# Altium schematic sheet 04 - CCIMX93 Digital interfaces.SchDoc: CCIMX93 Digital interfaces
size A3; PageSetup: Record=PageOptions¦CenterHorizontal=True¦CenterVertical=True¦PrintScale=0.70¦XCorrection=1.00¦YCorrection=1.00¦PrintKind=0¦BorderSize=5000000¦LeftOffset=0¦BottomOffset=0¦Orientation=2¦PaperLength=4200¦PaperWidth=2970¦Scale=100¦PaperSource=7¦PrintQuality=600¦MediaType=1¦DitherType=10¦PaperKind=A4¦PrintScaleMode=1; Author: Juan Anzola; SheetNumber: 4; SheetTotal: 20
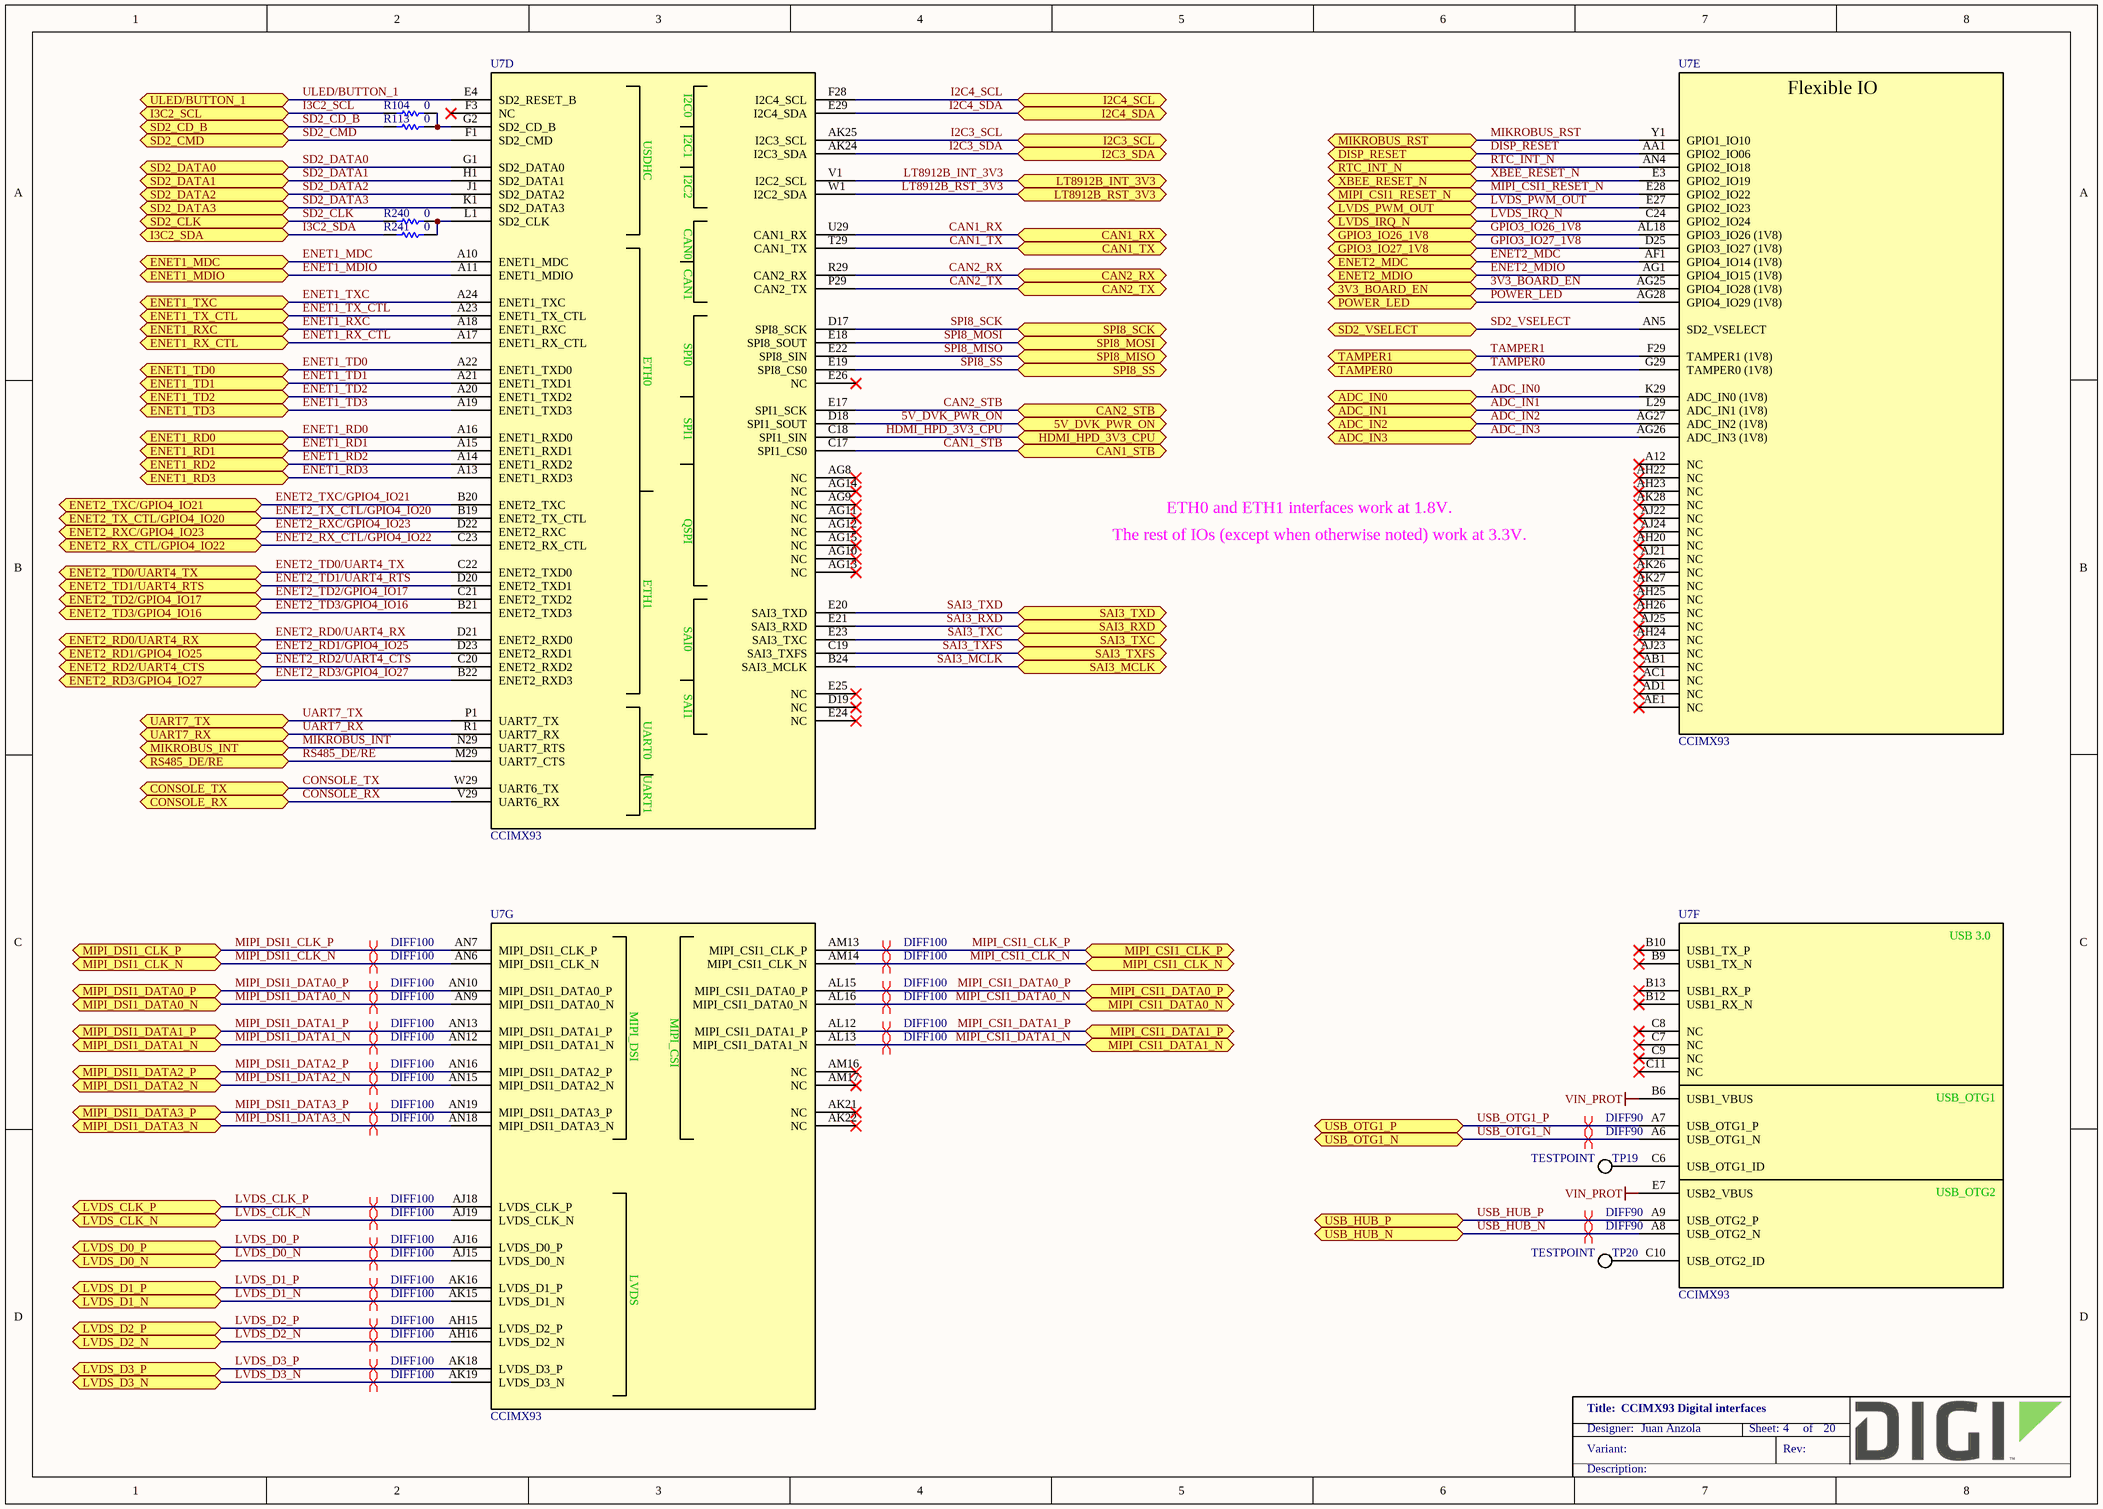
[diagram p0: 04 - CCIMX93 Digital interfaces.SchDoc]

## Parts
R104  0  [RESC1005X40N]
R113  0  [RESC1005X40N]
R240  0  [RESC1005X40N]
R241  0  [RESC1005X40N]
TP19  TESTPOINT  [TP0762]  (no BOM)
TP20  TESTPOINT  [TP0762]  (no BOM)
U7  CCIMX93  [CC93_DVK]  (parts D,E,F,G of 10)

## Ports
3V3_BOARD_EN (bidir), 5V_DVK_PWR_ON (bidir), ADC_IN0 (bidir), ADC_IN1 (bidir), ADC_IN2 (bidir), ADC_IN3 (bidir), CAN1_RX (bidir), CAN1_STB (bidir), CAN1_TX (bidir), CAN2_RX (bidir), CAN2_STB (bidir), CAN2_TX (bidir), CONSOLE_RX (bidir), CONSOLE_TX (bidir), DISP_RESET (bidir), ENET1_MDC (bidir), ENET1_MDIO (bidir), ENET1_RD0 (bidir), ENET1_RD1 (bidir), ENET1_RD2 (bidir), ENET1_RD3 (bidir), ENET1_RX_CTL (bidir), ENET1_RXC (bidir), ENET1_TD0 (bidir), ENET1_TD1 (bidir), ENET1_TD2 (bidir), ENET1_TD3 (bidir), ENET1_TX_CTL (bidir), ENET1_TXC (bidir), ENET2_MDC (bidir), ENET2_MDIO (bidir), ENET2_RD0/UART4_RX (bidir), ENET2_RD1/GPIO4_IO25 (bidir), ENET2_RD2/UART4_CTS (bidir), ENET2_RD3/GPIO4_IO27 (bidir), ENET2_RX_CTL/GPIO4_IO22 (bidir), ENET2_RXC/GPIO4_IO23 (bidir), ENET2_TD0/UART4_TX (bidir), ENET2_TD1/UART4_RTS (bidir), ENET2_TD2/GPIO4_IO17 (bidir), ENET2_TD3/GPIO4_IO16 (bidir), ENET2_TX_CTL/GPIO4_IO20 (bidir), ENET2_TXC/GPIO4_IO21 (bidir), GPIO3_IO26_1V8 (bidir), GPIO3_IO27_1V8 (bidir), HDMI_HPD_3V3_CPU (bidir), I2C3_SCL (bidir), I2C3_SDA (bidir), I2C4_SCL (bidir), I2C4_SDA (bidir), I3C2_SCL (bidir), I3C2_SDA (bidir), LT8912B_INT_3V3 (bidir), LT8912B_RST_3V3 (bidir), LVDS_CLK_N (bidir), LVDS_CLK_P (bidir), LVDS_D0_N (bidir), LVDS_D0_P (bidir), LVDS_D1_N (bidir), LVDS_D1_P (bidir), LVDS_D2_N (bidir), LVDS_D2_P (bidir), LVDS_D3_N (bidir), LVDS_D3_P (bidir), LVDS_IRQ_N (bidir), LVDS_PWM_OUT (bidir), MIKROBUS_INT (bidir), MIKROBUS_RST (bidir), MIPI_CSI1_CLK_N (bidir), MIPI_CSI1_CLK_P (bidir), MIPI_CSI1_DATA0_N (bidir), MIPI_CSI1_DATA0_P (bidir), MIPI_CSI1_DATA1_N (bidir), MIPI_CSI1_DATA1_P (bidir), MIPI_CSI1_RESET_N (bidir), MIPI_DSI1_CLK_N (bidir), MIPI_DSI1_CLK_P (bidir), MIPI_DSI1_DATA0_N (bidir), MIPI_DSI1_DATA0_P (bidir), MIPI_DSI1_DATA1_N (bidir), MIPI_DSI1_DATA1_P (bidir), MIPI_DSI1_DATA2_N (bidir), MIPI_DSI1_DATA2_P (bidir), MIPI_DSI1_DATA3_N (bidir), MIPI_DSI1_DATA3_P (bidir), POWER_LED (bidir), RS485_DE/RE (bidir), RTC_INT_N (bidir), SAI3_MCLK (bidir), SAI3_RXD (bidir), SAI3_TXC (bidir), SAI3_TXD (bidir), SAI3_TXFS (bidir), SD2_CD_B (bidir), SD2_CLK (bidir), SD2_CMD (bidir), SD2_DATA0 (bidir), SD2_DATA1 (bidir), SD2_DATA2 (bidir), SD2_DATA3 (bidir), SD2_VSELECT (bidir), SPI8_MISO (bidir), SPI8_MOSI (bidir), SPI8_SCK (bidir), SPI8_SS (bidir), TAMPER0 (bidir), TAMPER1 (bidir), UART7_RX (bidir), UART7_TX (bidir), ULED/BUTTON_1 (bidir), USB_HUB_N (bidir), USB_HUB_P (bidir), USB_OTG1_N (bidir), USB_OTG1_P (bidir), XBEE_RESET_N (bidir)

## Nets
VIN_PROT: U7.B6(USB1_VBUS) U7.E7(USB2_VBUS)
3V3_BOARD_EN: U7.AG25(GPIO4_IO28_(1V8)) ; port 3V3_BOARD_EN
5V_DVK_PWR_ON: U7.D18(SPI1_SOUT) ; port 5V_DVK_PWR_ON
ADC_IN0: U7.K29(ADC_IN0_(1V8)) ; port ADC_IN0
ADC_IN1: U7.L29(ADC_IN1_(1V8)) ; port ADC_IN1
ADC_IN2: U7.AG27(ADC_IN2_(1V8)) ; port ADC_IN2
ADC_IN3: U7.AG26(ADC_IN3_(1V8)) ; port ADC_IN3
CAN1_RX: U7.U29(CAN1_RX) ; port CAN1_RX
CAN1_STB: U7.C17(SPI1_CS0) ; port CAN1_STB
CAN1_TX: U7.T29(CAN1_TX) ; port CAN1_TX
CAN2_RX: U7.R29(CAN2_RX) ; port CAN2_RX
CAN2_STB: U7.E17(SPI1_SCK) ; port CAN2_STB
CAN2_TX: U7.P29(CAN2_TX) ; port CAN2_TX
CONSOLE_RX: U7.V29(UART6_RX) ; port CONSOLE_RX
CONSOLE_TX: U7.W29(UART6_TX) ; port CONSOLE_TX
DISP_RESET: U7.AA1(GPIO2_IO06) ; port DISP_RESET
ENET1_MDC: U7.A10(ENET1_MDC) ; port ENET1_MDC
ENET1_MDIO: U7.A11(ENET1_MDIO) ; port ENET1_MDIO
ENET1_RD0: U7.A16(ENET1_RXD0) ; port ENET1_RD0
ENET1_RD1: U7.A15(ENET1_RXD1) ; port ENET1_RD1
ENET1_RD2: U7.A14(ENET1_RXD2) ; port ENET1_RD2
ENET1_RD3: U7.A13(ENET1_RXD3) ; port ENET1_RD3
ENET1_RX_CTL: U7.A17(ENET1_RX_CTL) ; port ENET1_RX_CTL
ENET1_RXC: U7.A18(ENET1_RXC) ; port ENET1_RXC
ENET1_TD0: U7.A22(ENET1_TXD0) ; port ENET1_TD0
ENET1_TD1: U7.A21(ENET1_TXD1) ; port ENET1_TD1
ENET1_TD2: U7.A20(ENET1_TXD2) ; port ENET1_TD2
ENET1_TD3: U7.A19(ENET1_TXD3) ; port ENET1_TD3
ENET1_TX_CTL: U7.A23(ENET1_TX_CTL) ; port ENET1_TX_CTL
ENET1_TXC: U7.A24(ENET1_TXC) ; port ENET1_TXC
ENET2_MDC: U7.AF1(GPIO4_IO14_(1V8)) ; port ENET2_MDC
ENET2_MDIO: U7.AG1(GPIO4_IO15_(1V8)) ; port ENET2_MDIO
ENET2_RD0/UART4_RX: U7.D21(ENET2_RXD0) ; port ENET2_RD0/UART4_RX
ENET2_RD1/GPIO4_IO25: U7.D23(ENET2_RXD1) ; port ENET2_RD1/GPIO4_IO25
ENET2_RD2/UART4_CTS: U7.C20(ENET2_RXD2) ; port ENET2_RD2/UART4_CTS
ENET2_RD3/GPIO4_IO27: U7.B22(ENET2_RXD3) ; port ENET2_RD3/GPIO4_IO27
ENET2_RX_CTL/GPIO4_IO22: U7.C23(ENET2_RX_CTL) ; port ENET2_RX_CTL/GPIO4_IO22
ENET2_RXC/GPIO4_IO23: U7.D22(ENET2_RXC) ; port ENET2_RXC/GPIO4_IO23
ENET2_TD0/UART4_TX: U7.C22(ENET2_TXD0) ; port ENET2_TD0/UART4_TX
ENET2_TD1/UART4_RTS: U7.D20(ENET2_TXD1) ; port ENET2_TD1/UART4_RTS
ENET2_TD2/GPIO4_IO17: U7.C21(ENET2_TXD2) ; port ENET2_TD2/GPIO4_IO17
ENET2_TD3/GPIO4_IO16: U7.B21(ENET2_TXD3) ; port ENET2_TD3/GPIO4_IO16
ENET2_TX_CTL/GPIO4_IO20: U7.B19(ENET2_TX_CTL) ; port ENET2_TX_CTL/GPIO4_IO20
ENET2_TXC/GPIO4_IO21: U7.B20(ENET2_TXC) ; port ENET2_TXC/GPIO4_IO21
GPIO3_IO26_1V8: U7.AL18(GPIO3_IO26_(1V8)) ; port GPIO3_IO26_1V8
GPIO3_IO27_1V8: U7.D25(GPIO3_IO27_(1V8)) ; port GPIO3_IO27_1V8
HDMI_HPD_3V3_CPU: U7.C18(SPI1_SIN) ; port HDMI_HPD_3V3_CPU
I2C3_SCL: U7.AK25(I2C3_SCL) ; port I2C3_SCL
I2C3_SDA: U7.AK24(I2C3_SDA) ; port I2C3_SDA
I2C4_SCL: U7.F28(I2C4_SCL) ; port I2C4_SCL
I2C4_SDA: U7.E29(I2C4_SDA) ; port I2C4_SDA
I3C2_SCL: R104.1 ; port I3C2_SCL
I3C2_SDA: R241.1 ; port I3C2_SDA
LT8912B_INT_3V3: U7.V1(I2C2_SCL) ; port LT8912B_INT_3V3
LT8912B_RST_3V3: U7.W1(I2C2_SDA) ; port LT8912B_RST_3V3
LVDS_CLK_N: U7.AJ19(LVDS_CLK_N) ; port LVDS_CLK_N
LVDS_CLK_P: U7.AJ18(LVDS_CLK_P) ; port LVDS_CLK_P
LVDS_D0_N: U7.AJ15(LVDS_D0_N) ; port LVDS_D0_N
LVDS_D0_P: U7.AJ16(LVDS_D0_P) ; port LVDS_D0_P
LVDS_D1_N: U7.AK15(LVDS_D1_N) ; port LVDS_D1_N
LVDS_D1_P: U7.AK16(LVDS_D1_P) ; port LVDS_D1_P
LVDS_D2_N: U7.AH16(LVDS_D2_N) ; port LVDS_D2_N
LVDS_D2_P: U7.AH15(LVDS_D2_P) ; port LVDS_D2_P
LVDS_D3_N: U7.AK19(LVDS_D3_N) ; port LVDS_D3_N
LVDS_D3_P: U7.AK18(LVDS_D3_P) ; port LVDS_D3_P
LVDS_IRQ_N: U7.C24(GPIO2_IO24) ; port LVDS_IRQ_N
LVDS_PWM_OUT: U7.E27(GPIO2_IO23) ; port LVDS_PWM_OUT
MIKROBUS_INT: U7.N29(UART7_RTS) ; port MIKROBUS_INT
MIKROBUS_RST: U7.Y1(GPIO1_IO10) ; port MIKROBUS_RST
MIPI_CSI1_CLK_N: U7.AM14(MIPI_CSI1_CLK_N) ; port MIPI_CSI1_CLK_N
MIPI_CSI1_CLK_P: U7.AM13(MIPI_CSI1_CLK_P) ; port MIPI_CSI1_CLK_P
MIPI_CSI1_DATA0_N: U7.AL16(MIPI_CSI1_DATA0_N) ; port MIPI_CSI1_DATA0_N
MIPI_CSI1_DATA0_P: U7.AL15(MIPI_CSI1_DATA0_P) ; port MIPI_CSI1_DATA0_P
MIPI_CSI1_DATA1_N: U7.AL13(MIPI_CSI1_DATA1_N) ; port MIPI_CSI1_DATA1_N
MIPI_CSI1_DATA1_P: U7.AL12(MIPI_CSI1_DATA1_P) ; port MIPI_CSI1_DATA1_P
MIPI_CSI1_RESET_N: U7.E28(GPIO2_IO22) ; port MIPI_CSI1_RESET_N
MIPI_DSI1_CLK_N: U7.AN6(MIPI_DSI1_CLK_N) ; port MIPI_DSI1_CLK_N
MIPI_DSI1_CLK_P: U7.AN7(MIPI_DSI1_CLK_P) ; port MIPI_DSI1_CLK_P
MIPI_DSI1_DATA0_N: U7.AN9(MIPI_DSI1_DATA0_N) ; port MIPI_DSI1_DATA0_N
MIPI_DSI1_DATA0_P: U7.AN10(MIPI_DSI1_DATA0_P) ; port MIPI_DSI1_DATA0_P
MIPI_DSI1_DATA1_N: U7.AN12(MIPI_DSI1_DATA1_N) ; port MIPI_DSI1_DATA1_N
MIPI_DSI1_DATA1_P: U7.AN13(MIPI_DSI1_DATA1_P) ; port MIPI_DSI1_DATA1_P
MIPI_DSI1_DATA2_N: U7.AN15(MIPI_DSI1_DATA2_N) ; port MIPI_DSI1_DATA2_N
MIPI_DSI1_DATA2_P: U7.AN16(MIPI_DSI1_DATA2_P) ; port MIPI_DSI1_DATA2_P
MIPI_DSI1_DATA3_N: U7.AN18(MIPI_DSI1_DATA3_N) ; port MIPI_DSI1_DATA3_N
MIPI_DSI1_DATA3_P: U7.AN19(MIPI_DSI1_DATA3_P) ; port MIPI_DSI1_DATA3_P
POWER_LED: U7.AG28(GPIO4_IO29_(1V8)) ; port POWER_LED
RS485_DE/RE: U7.M29(UART7_CTS) ; port RS485_DE/RE
RTC_INT_N: U7.AN4(GPIO2_IO18) ; port RTC_INT_N
SAI3_MCLK: U7.B24(SAI3_MCLK) ; port SAI3_MCLK
SAI3_RXD: U7.E21(SAI3_RXD) ; port SAI3_RXD
SAI3_TXC: U7.E23(SAI3_TXC) ; port SAI3_TXC
SAI3_TXD: U7.E20(SAI3_TXD) ; port SAI3_TXD
SAI3_TXFS: U7.C19(SAI3_TXFS) ; port SAI3_TXFS
SD2_CD_B: R113.1 ; port SD2_CD_B
SD2_CLK: R240.1 ; port SD2_CLK
SD2_CMD: U7.F1(SD2_CMD) ; port SD2_CMD
SD2_DATA0: U7.G1(SD2_DATA0) ; port SD2_DATA0
SD2_DATA1: U7.H1(SD2_DATA1) ; port SD2_DATA1
SD2_DATA2: U7.J1(SD2_DATA2) ; port SD2_DATA2
SD2_DATA3: U7.K1(SD2_DATA3) ; port SD2_DATA3
SD2_VSELECT: U7.AN5(SD2_VSELECT) ; port SD2_VSELECT
SPI8_MISO: U7.E22(SPI8_SIN) ; port SPI8_MISO
SPI8_MOSI: U7.E18(SPI8_SOUT) ; port SPI8_MOSI
SPI8_SCK: U7.D17(SPI8_SCK) ; port SPI8_SCK
SPI8_SS: U7.E19(SPI8_CS0) ; port SPI8_SS
TAMPER0: U7.G29(TAMPER0_(1V8)) ; port TAMPER0
TAMPER1: U7.F29(TAMPER1_(1V8)) ; port TAMPER1
UART7_RX: U7.R1(UART7_RX) ; port UART7_RX
UART7_TX: U7.P1(UART7_TX) ; port UART7_TX
ULED/BUTTON_1: U7.E4(SD2_RESET_B) ; port ULED/BUTTON_1
USB_HUB_N: U7.A8(USB_OTG2_N) ; port USB_HUB_N
USB_HUB_P: U7.A9(USB_OTG2_P) ; port USB_HUB_P
USB_OTG1_N: U7.A6(USB_OTG1_N) ; port USB_OTG1_N
USB_OTG1_P: U7.A7(USB_OTG1_P) ; port USB_OTG1_P
XBEE_RESET_N: U7.E3(GPIO2_IO19) ; port XBEE_RESET_N
NetR104_2: R104.2 R113.2 U7.G2(SD2_CD_B)
NetR240_2: R240.2 R241.2 U7.L1(SD2_CLK)
NetTP19_1: TP19.1 U7.C6(USB_OTG1_ID)
NetTP20_1: TP20.1 U7.C10(USB_OTG2_ID)

Not connected (* = marked no-connect by the designer): U7 A12(NC)* AB1(NC)* AC1(NC)* AD1(NC)* AE1(NC)* AG8(NC)* AG9(NC)* AG10(NC)* AG11(NC)* AG12(NC)* AG13(NC)* AG14(NC)* AG15(NC)* AH20(NC)* AH22(NC)* AH23(NC)* AH24(NC)* AH25(NC)* AH26(NC)* AJ21(NC)* AJ22(NC)* AJ23(NC)* AJ24(NC)* AJ25(NC)* AK21(NC)* AK22(NC)* AK26(NC)* AK27(NC)* AK28(NC)* AM16(NC)* AM17(NC)* B9(USB1_TX_N)* B10(USB1_TX_P)* B12(USB1_RX_N)* B13(USB1_RX_P)* C7(NC)* C8(NC)* C9(NC)* C11(NC)* D19(NC)* E24(NC)* E25(NC)* E26(NC)* F3(NC)*

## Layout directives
differential pair; net class DIFF100; differential pair class DIFF100: LVDS_CLK_N, LVDS_CLK_P, LVDS_D0_N, LVDS_D0_P, LVDS_D1_N, LVDS_D1_P, LVDS_D2_N, LVDS_D2_P, LVDS_D3_N, LVDS_D3_P, MIPI_CSI1_CLK_N, MIPI_CSI1_CLK_P, MIPI_CSI1_DATA0_N, MIPI_CSI1_DATA0_P, MIPI_CSI1_DATA1_N, MIPI_CSI1_DATA1_P, MIPI_DSI1_CLK_N, MIPI_DSI1_CLK_P, MIPI_DSI1_DATA0_N, MIPI_DSI1_DATA0_P, MIPI_DSI1_DATA1_N, MIPI_DSI1_DATA1_P, MIPI_DSI1_DATA2_N, MIPI_DSI1_DATA2_P, MIPI_DSI1_DATA3_N, MIPI_DSI1_DATA3_P
differential pair; net class DIFF90; differential pair class DIFF90: USB_HUB_N, USB_HUB_P, USB_OTG1_N, USB_OTG1_P

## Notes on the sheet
- ETH0 and ETH1 interfaces work at 1.8V.
- The rest of IOs (except when otherwise noted) work at 3.3V.

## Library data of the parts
R104 R113 R240 R241 = 1000076: RES 0.0 OHM 1/10W 0402 SMD; Part_Type: Resistor; Manufacturer: Panasonic - ECG; Manufacturer_Part_Number: ERJ-2GE0R00X; Digi_PN: 13050387; Component_Life_Cycle_State: Proven; Area: 0,95; Power_WV_SRF: 10
TP19 TP20 = CAD0011: TEST POINT 30MIL PAD SMT; Component_Life_Cycle_State: Reviewed; Area: 0,58; Project: CLC
U7 = 1002856: ConnectCore for i.MX93 module; Manufacturer: DIGI; Digi_PN: 55002169-01; Component_Life_Cycle_State: Pending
